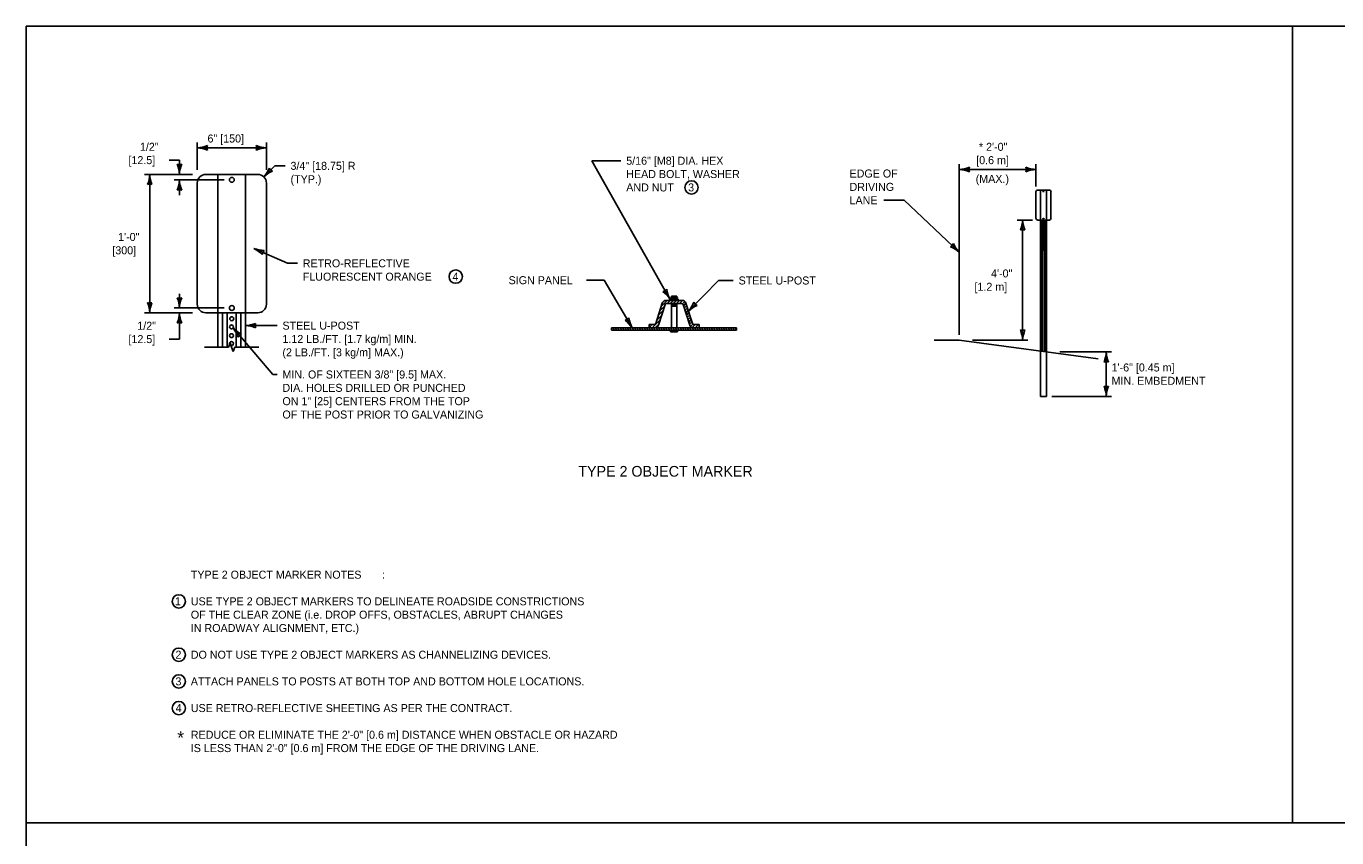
# Model space of a CAD drawing. Extents: x 49991.4 to 50024.6, y 49987.6 to 50011.4.
# Drawn here: x 49999.38 to 50009.21, y 49992.92 to 49999 of the extents above; entities that cross this region are included whole.
import ezdxf

# ---------------------------------------------------------------- set-up
doc = ezdxf.new("R2010")
doc.units = 0
for name, color, linetype in [('Level 1', 7, 'Continuous'), ('Level 2', 7, 'Continuous'), ('Level 3', 7, 'Continuous'), ('Level 4', 7, 'Continuous'), ('Level 6', 7, 'Continuous')]:
    doc.layers.add(name, color=color, linetype=linetype)

msp = doc.modelspace()

# ---------------------------------------------------------------- linework, layer by layer
at = {"layer": 'Level 1'}
for p, q in [((50006.9969, 49996.563), (50006.9969, 49997.5461)), ((50007.0044, 49996.562), (50007.0044, 49997.5461)), ((50007.0194, 49996.56), (50007.0194, 49997.5461)), ((50007.0269, 49996.5592), (50007.0269, 49997.5461)), ((50004.1345, 49996.8647), (50004.1709, 49996.9011)), ((50004.1455, 49996.8987), (50004.1904, 49996.9437)), ((50004.1899, 49996.9202), (50004.2134, 49996.9437)), ((50004.2107, 49996.9538), (50004.2733, 49996.9538)), ((50004.2107, 49996.9538), (50004.2107, 49996.9437)), ((50004.2131, 49996.9202), (50004.2366, 49996.9437)), ((50004.2166, 49996.9648), (50004.2674, 49996.9648)), ((50004.2166, 49996.9648), (50004.2166, 49996.9538)), ((50004.2224, 49996.975), (50004.2615, 49996.975)), ((50004.2224, 49996.975), (50004.2224, 49996.9648)), ((50004.2322, 49996.9699), (50004.2518, 49996.9699)), ((50004.2322, 49996.9151), (50004.2518, 49996.9151)), ((50004.2322, 49996.9048), (50004.2518, 49996.9048)), ((50004.2334, 49996.9648), (50004.2334, 49996.9538)), ((50004.2362, 49996.9202), (50004.2597, 49996.9437)), ((50004.2505, 49996.9648), (50004.2505, 49996.9538)), ((50004.2592, 49996.9202), (50004.2827, 49996.9437)), ((50004.2615, 49996.975), (50004.2615, 49996.9648)), ((50004.2674, 49996.9648), (50004.2674, 49996.9538)), ((50004.2733, 49996.9538), (50004.2733, 49996.9437)), ((50004.2822, 49996.9202), (50004.3056, 49996.9435)), ((50004.3039, 49996.9188), (50004.3217, 49996.9366)), ((50004.3121, 49996.9039), (50004.3308, 49996.9225)), ((50004.3178, 49996.8865), (50004.3364, 49996.9051)), ((50004.3234, 49996.8691), (50004.342, 49996.8878)), ((50000.8548, 49996.5938), (50000.8548, 49996.8508)), ((50000.8894, 49996.5938), (50000.8894, 49996.8508)), ((50000.9587, 49996.5938), (50000.9587, 49996.8508)), ((50000.9933, 49996.5938), (50000.9933, 49996.8508)), ((50004.0775, 49996.7385), (50004.138, 49996.7989)), ((50004.1124, 49996.7964), (50004.149, 49996.833)), ((50004.1234, 49996.8305), (50004.1599, 49996.8669)), ((50004.329, 49996.8517), (50004.3476, 49996.8704)), ((50004.3347, 49996.8342), (50004.3533, 49996.8528)), ((50004.3403, 49996.8168), (50004.3589, 49996.8355)), ((50004.3459, 49996.7994), (50004.3645, 49996.8181)), ((50004.3516, 49996.7819), (50004.3702, 49996.8005)), ((50004.3572, 49996.7645), (50004.3758, 49996.7831)), ((50003.7732, 49996.7272), (50003.7796, 49996.7209)), ((50003.7799, 49996.7385), (50003.7976, 49996.7209)), ((50003.7979, 49996.7385), (50003.8156, 49996.7209)), ((50003.8159, 49996.7385), (50003.8336, 49996.7209)), ((50003.8339, 49996.7385), (50003.8516, 49996.7209)), ((50003.8519, 49996.7385), (50003.8696, 49996.7209)), ((50003.8699, 49996.7385), (50003.8876, 49996.7209)), ((50003.8879, 49996.7385), (50003.9056, 49996.7209)), ((50003.9059, 49996.7385), (50003.9236, 49996.7209)), ((50003.9239, 49996.7385), (50003.9416, 49996.7209)), ((50003.9419, 49996.7385), (50003.9596, 49996.7209)), ((50003.9599, 49996.7385), (50003.9776, 49996.7209)), ((50003.9779, 49996.7385), (50003.9956, 49996.7209)), ((50003.9959, 49996.7385), (50004.0136, 49996.7209)), ((50004.0139, 49996.7385), (50004.0316, 49996.7209)), ((50004.0319, 49996.7385), (50004.0496, 49996.7209)), ((50004.0499, 49996.7385), (50004.0676, 49996.7209)), ((50004.0545, 49996.7385), (50004.078, 49996.762)), ((50004.0679, 49996.7385), (50004.0856, 49996.7209)), ((50004.0859, 49996.7385), (50004.1036, 49996.7209)), ((50004.1008, 49996.7387), (50004.127, 49996.765)), ((50004.1039, 49996.7385), (50004.1216, 49996.7209)), ((50004.1219, 49996.7385), (50004.1396, 49996.7209)), ((50004.1399, 49996.7385), (50004.1576, 49996.7209)), ((50004.1579, 49996.7385), (50004.1756, 49996.7209)), ((50004.1759, 49996.7385), (50004.1936, 49996.7209)), ((50004.1939, 49996.7385), (50004.2116, 49996.7209)), ((50004.2119, 49996.7385), (50004.2296, 49996.7209)), ((50004.2152, 49996.7209), (50004.2152, 49996.7091)), ((50004.2152, 49996.7091), (50004.2666, 49996.7091)), ((50004.2299, 49996.7385), (50004.2476, 49996.7209)), ((50004.2333, 49996.7209), (50004.2333, 49996.7091)), ((50004.2479, 49996.7385), (50004.2656, 49996.7209)), ((50004.251, 49996.7209), (50004.251, 49996.7091)), ((50004.2659, 49996.7385), (50004.2836, 49996.7209)), ((50004.2666, 49996.7209), (50004.2666, 49996.7091)), ((50004.2839, 49996.7385), (50004.3016, 49996.7209)), ((50004.3019, 49996.7385), (50004.3196, 49996.7209)), ((50004.3199, 49996.7385), (50004.3376, 49996.7209)), ((50004.3379, 49996.7385), (50004.3556, 49996.7209)), ((50004.3559, 49996.7385), (50004.3736, 49996.7209)), ((50004.3645, 49996.7489), (50004.382, 49996.7664)), ((50004.3739, 49996.7385), (50004.3916, 49996.7209)), ((50004.3784, 49996.7397), (50004.4006, 49996.762)), ((50004.3919, 49996.7385), (50004.4096, 49996.7209)), ((50004.4003, 49996.7385), (50004.4238, 49996.762)), ((50004.4099, 49996.7385), (50004.4276, 49996.7209)), ((50004.4233, 49996.7385), (50004.4295, 49996.7447)), ((50004.4279, 49996.7385), (50004.4456, 49996.7209)), ((50004.4459, 49996.7385), (50004.4636, 49996.7209)), ((50004.4639, 49996.7385), (50004.4816, 49996.7209)), ((50004.4819, 49996.7385), (50004.4996, 49996.7209)), ((50004.4999, 49996.7385), (50004.5176, 49996.7209)), ((50004.5179, 49996.7385), (50004.5356, 49996.7209)), ((50004.5359, 49996.7385), (50004.5536, 49996.7209)), ((50004.5539, 49996.7385), (50004.5716, 49996.7209)), ((50004.5719, 49996.7385), (50004.5896, 49996.7209)), ((50004.5899, 49996.7385), (50004.6076, 49996.7209)), ((50004.6079, 49996.7385), (50004.6256, 49996.7209)), ((50004.6259, 49996.7385), (50004.6436, 49996.7209)), ((50004.6439, 49996.7385), (50004.6616, 49996.7209)), ((50004.6619, 49996.7385), (50004.6796, 49996.7209)), ((50004.6799, 49996.7385), (50004.6976, 49996.7209)), ((50004.6979, 49996.7385), (50004.7106, 49996.7258))]:
    msp.add_line(p, q, dxfattribs=at)
msp.add_lwpolyline([(49999.3835, 49998.9992), (50016.7501, 49998.9992), (50016.7501, 49987.7988), (49999.3835, 49987.7988)], close=True, dxfattribs=at)
for centre, radius in [((50007.0116, 49997.5231), 0.00318), ((50007.0116, 49997.509), 0.00318), ((50007.0116, 49997.4956), 0.00318), ((50007.0116, 49997.4823), 0.00318), ((50007.0116, 49997.4689), 0.00318), ((50007.012, 49997.5365), 0.00318), ((50007.0116, 49997.4556), 0.00318), ((50007.0116, 49997.4422), 0.00318), ((50007.0116, 49997.4289), 0.00318), ((50007.0116, 49997.4155), 0.00318), ((50007.0116, 49997.4022), 0.00318), ((50007.0116, 49997.3888), 0.00318), ((50007.0116, 49997.3755), 0.00318), ((50007.0116, 49997.3621), 0.00318), ((50007.0116, 49997.3488), 0.00318), ((50007.0116, 49997.3354), 0.00318), ((50007.0116, 49997.3221), 0.00318), ((50000.9247, 49996.8065), 0.0146), ((50000.9229, 49996.745), 0.0146), ((50000.9229, 49996.6798), 0.0146)]:
    msp.add_circle(centre, radius, dxfattribs=at)
msp.add_arc((50000.9229, 49996.6201), 0.0146, 258.06006, 198.90955, dxfattribs=at)
at = {"layer": 'Level 2'}
for p, q in [((50008.8796, 49998.9992), (50008.8796, 49993.0275)), ((50000.7308, 49997.8885), (50001.1201, 49997.8885)), ((50000.666, 49996.9156), (50000.666, 49997.8237)), ((50001.185, 49997.8237), (50001.185, 49996.9156)), ((50006.97, 49997.7711), (50007.0544, 49997.7711)), ((50006.9559, 49997.5601), (50006.9559, 49997.757)), ((50007.0684, 49997.757), (50007.0684, 49997.5601)), ((50007.0544, 49997.5461), (50006.97, 49997.5461)), ((50006.9894, 49996.564), (50006.9894, 49997.5461)), ((50007.0344, 49996.558), (50007.0344, 49997.5461)), ((50004.1534, 49996.9234), (50004.1039, 49996.7701)), ((50004.1744, 49996.9121), (50004.125, 49996.7587)), ((50004.1812, 49996.9437), (50004.3027, 49996.9437)), ((50004.1856, 49996.9202), (50004.2984, 49996.9202)), ((50004.2224, 49996.9202), (50004.2224, 49996.7385)), ((50004.2224, 49996.9099), (50004.2615, 49996.9099)), ((50004.2224, 49996.8997), (50004.2615, 49996.8997)), ((50004.2615, 49996.9202), (50004.2615, 49996.7385)), ((50004.3095, 49996.9121), (50004.3591, 49996.7587)), ((50004.3305, 49996.9235), (50004.38, 49996.7701)), ((50001.1201, 49996.8508), (50000.7308, 49996.8508)), ((50000.8203, 49996.5938), (50000.8203, 49996.8508)), ((50001.0278, 49996.5938), (50001.0278, 49996.8508)), ((50003.7732, 49996.7385), (50003.7732, 49996.7209)), ((50003.7732, 49996.7385), (50004.7107, 49996.7385)), ((50003.7732, 49996.7209), (50004.7107, 49996.7209)), ((50004.0544, 49996.762), (50004.0544, 49996.7385)), ((50004.0544, 49996.762), (50004.0928, 49996.762)), ((50004.0971, 49996.7385), (50004.0544, 49996.7385)), ((50004.3868, 49996.7385), (50004.4295, 49996.7385)), ((50004.3912, 49996.762), (50004.4295, 49996.762)), ((50004.4295, 49996.762), (50004.4295, 49996.7385)), ((50004.7107, 49996.7385), (50004.7107, 49996.7209)), ((50006.3806, 49996.6461), (50006.1934, 49996.6461)), ((50006.3806, 49996.6461), (50007.4228, 49996.5056)), ((49999.3835, 49993.0275), (50016.7501, 49993.0275))]:
    msp.add_line(p, q, dxfattribs=at)
for centre, radius in [((50000.9255, 49997.8474), 0.0183), ((50004.3724, 49997.7909), 0.05), ((50007.0122, 49997.7621), 0.00397), ((50007.0121, 49997.554), 0.00397), ((50002.6043, 49997.1218), 0.05), ((50000.9251, 49996.8873), 0.0183), ((50000.5279, 49994.6878), 0.05), ((50000.5279, 49994.2878), 0.05), ((50000.5279, 49994.0878), 0.05), ((50000.5279, 49993.8878), 0.05)]:
    msp.add_circle(centre, radius, dxfattribs=at)
for centre, radius, start, end in [((50000.7308, 49997.8237), 0.0648, 90, 180), ((50001.1201, 49997.8237), 0.0648, 0, 90), ((50006.97, 49997.757), 0.0141, 90, 180), ((50007.0544, 49997.757), 0.0141, 0, 90), ((50006.97, 49997.5601), 0.0141, 180, 270), ((50007.0544, 49997.5601), 0.0141, 270, 0), ((50000.7308, 49996.9156), 0.0648, 180, 270), ((50001.1201, 49996.9156), 0.0648, 270, 0), ((50004.1813, 49996.9144), 0.0293, 90, 162.11094), ((50004.1856, 49996.9084), 0.0117, 90, 162.11105), ((50004.2983, 49996.9084), 0.0117, 17.88895, 90), ((50004.3027, 49996.9144), 0.0293, 17.88906, 90), ((50004.0928, 49996.7737), 0.0117, 270, 342.11094), ((50004.0972, 49996.7677), 0.0293, 270, 342.11105), ((50004.3869, 49996.7677), 0.0293, 197.88804, 270), ((50004.3912, 49996.7737), 0.0117, 197.88906, 270.15232)]:
    msp.add_arc(centre, radius, start, end, dxfattribs=at)
at = {"layer": 'Level 3'}
for p, q in [((50000.666, 49997.9237), (50000.666, 49998.1275)), ((50001.185, 49998.0875), (50000.666, 49998.0875)), ((50001.185, 49997.9237), (50001.185, 49998.1275)), ((50000.4544, 49997.9954), (50000.5325, 49997.9954)), ((50000.5325, 49997.8885), (50000.5325, 49997.9954)), ((50004.2107, 49996.9538), (50003.6257, 49997.9909)), ((50003.6257, 49997.9909), (50003.8432, 49997.9909)), ((50006.3806, 49997.9651), (50006.3806, 49996.6861)), ((50006.9559, 49997.797), (50006.9559, 49997.9651)), ((50000.6308, 49997.8885), (50000.2698, 49997.8885)), ((50000.3098, 49996.8508), (50000.3098, 49997.8885)), ((50001.1652, 49997.8703), (50001.2474, 49997.9525)), ((50001.2474, 49997.9525), (50001.3255, 49997.9525)), ((50006.9559, 49997.9251), (50006.3806, 49997.9251)), ((50000.8672, 49997.8474), (50000.4925, 49997.8474)), ((50000.5325, 49997.7837), (50000.5325, 49997.8474)), ((50000.5325, 49997.8474), (50000.5325, 49997.7329)), ((50005.9678, 49997.695), (50005.8146, 49997.695)), ((50005.9678, 49997.695), (50006.3806, 49997.3054)), ((50006.93, 49997.5461), (50006.8159, 49997.5461)), ((50006.8559, 49997.5461), (50006.8559, 49996.6461)), ((50001.3427, 49997.2218), (50001.0908, 49997.3336)), ((50001.4174, 49997.2218), (50001.3427, 49997.2218)), ((50003.7178, 49997.0952), (50003.5849, 49997.0952)), ((50003.7178, 49997.0952), (50003.9273, 49996.7385)), ((50004.5741, 49997.0931), (50004.3497, 49996.8639)), ((50004.5741, 49997.0931), (50004.6858, 49997.0931)), ((50000.5325, 49996.8873), (50000.5325, 49996.9943)), ((50000.8668, 49996.8873), (50000.4925, 49996.8873)), ((50000.5325, 49996.9555), (50000.5325, 49996.8918)), ((50000.6308, 49996.8508), (50000.2698, 49996.8508)), ((50000.5325, 49996.8508), (50000.5325, 49996.6538)), ((50001.2336, 49996.3884), (50000.9353, 49996.7373)), ((50001.2649, 49996.7547), (50001.0278, 49996.7547)), ((50000.4544, 49996.6538), (50000.5325, 49996.6538)), ((50006.4806, 49996.6461), (50006.8959, 49996.6461)), ((50007.1344, 49996.558), (50007.5229, 49996.558)), ((50007.4829, 49996.2242), (50007.4829, 49996.558)), ((50001.2649, 49996.3884), (50001.2336, 49996.3884)), ((50007.0744, 49996.2242), (50007.5229, 49996.2242))]:
    msp.add_line(p, q, dxfattribs=at)
for centre, radius, start, end in [((50000.6545, 49998.3203), 0.233, 272.82731, 292.07716), ((50000.6568, 49997.8654), 0.2223, 67.45601, 87.63952), ((50000.7942, 49998.0875), 0.0548, 162.13882, 197.86118), ((50001.1941, 49998.3097), 0.2223, 247.45601, 267.63952), ((50001.0568, 49998.0875), 0.0548, 342.13882, 17.86118), ((50001.1965, 49997.8548), 0.233, 92.82731, 112.07716), ((50000.5325, 49998.0168), 0.0548, 252.13882, 287.86118), ((50000.2998, 49997.877), 0.233, 2.82731, 22.07716), ((50000.7547, 49997.8794), 0.2223, 157.45601, 177.63952), ((50000.0876, 49997.8977), 0.2223, 337.45601, 357.63952), ((50000.5425, 49997.9), 0.233, 182.82731, 202.07716), ((50000.9925, 49998.0267), 0.233, 317.82731, 337.07716), ((50001.3158, 49997.7068), 0.2223, 112.45601, 132.63952), ((50001.2559, 49997.961), 0.0548, 207.13882, 242.86118), ((50006.3691, 49998.1578), 0.233, 272.82731, 292.07716), ((50006.3714, 49997.703), 0.2223, 67.45601, 87.63952), ((50006.5088, 49997.9251), 0.0548, 162.13882, 197.86118), ((50006.9651, 49998.1473), 0.2223, 247.45601, 267.63952), ((50006.8277, 49997.9251), 0.0548, 342.13882, 17.86118), ((50006.9674, 49997.6924), 0.233, 92.82731, 112.07716), ((50000.3098, 49997.7603), 0.0548, 72.13882, 107.86118), ((50000.3104, 49997.8565), 0.2223, 337.45601, 357.63952), ((50000.5325, 49997.7192), 0.0548, 72.13882, 107.86118), ((50000.7652, 49997.8589), 0.233, 182.82731, 202.07716), ((50006.6338, 49997.5552), 0.2223, 337.45601, 357.63952), ((50006.8559, 49997.4179), 0.0548, 72.13882, 107.86118), ((50007.0886, 49997.5576), 0.233, 182.82731, 202.07716), ((50000.9923, 49997.1343), 0.2223, 43.52413, 63.70764), ((50001.1747, 49997.551), 0.233, 248.89543, 268.14528), ((50001.2079, 49997.2816), 0.0548, 138.20694, 173.9293), ((50006.2873, 49997.3934), 0.0548, 298.79497, 334.51733), ((50006.2292, 49997.1283), 0.233, 49.48346, 68.73331), ((50006.5397, 49997.4607), 0.2223, 204.11216, 224.29567), ((50004.1477, 49997.0654), 0.0548, 281.56499, 317.28735), ((50004.0137, 49996.8294), 0.233, 32.25348, 51.50333), ((50004.4087, 49997.0549), 0.2223, 186.88218, 207.06569), ((50000.3098, 49996.979), 0.0548, 252.13882, 287.86118), ((50000.0771, 49996.8393), 0.233, 2.82731, 22.07716), ((50000.5319, 49996.8416), 0.2223, 157.45601, 177.63952), ((50000.3104, 49996.8781), 0.2223, 2.36048, 22.54399), ((50000.5325, 49997.0155), 0.0548, 252.13882, 287.86118), ((50000.7652, 49996.8758), 0.233, 157.92284, 177.17269), ((50004.1754, 49997.0185), 0.233, 318.43466, 337.68451), ((50004.5021, 49996.7019), 0.2223, 113.06336, 133.24687), ((50004.4394, 49996.9555), 0.0548, 207.74617, 243.46853), ((50000.2998, 49996.8623), 0.233, 337.92284, 357.17269), ((50000.7547, 49996.8599), 0.2223, 182.36048, 202.54399), ((50003.8624, 49996.849), 0.0548, 282.56173, 318.28409), ((50003.7325, 49996.6107), 0.233, 33.25022, 52.50007), ((50004.1235, 49996.8431), 0.2223, 187.87892, 208.06243), ((50000.5325, 49996.7226), 0.0548, 72.13882, 107.86118), ((50000.7605, 49996.5999), 0.2223, 17.98835, 38.17186), ((50001.1047, 49996.8972), 0.233, 223.35965, 242.6095), ((50001.0186, 49996.6398), 0.0548, 112.67116, 148.39352), ((50001.0163, 49996.9874), 0.233, 272.82731, 292.07716), ((50001.0187, 49996.5326), 0.2223, 67.45601, 87.63952), ((50001.156, 49996.7547), 0.0548, 162.13882, 197.86118), ((50006.8559, 49996.7743), 0.0548, 252.13882, 287.86118), ((50006.6232, 49996.6346), 0.233, 2.82731, 22.07716), ((50007.0781, 49996.6369), 0.2223, 157.45601, 177.63952), ((50007.2608, 49996.5671), 0.2223, 337.45601, 357.63952), ((50007.7156, 49996.5695), 0.233, 182.82731, 202.07716), ((50007.4829, 49996.4297), 0.0548, 72.13882, 107.86118), ((50007.4829, 49996.3524), 0.0548, 252.13882, 287.86118), ((50007.2502, 49996.2127), 0.233, 2.82731, 22.07716), ((50007.7051, 49996.2151), 0.2223, 157.45601, 177.63952)]:
    msp.add_arc(centre, radius, start, end, dxfattribs=at)
at = {"layer": 'Level 4'}
for p, q in [((50000.8203, 49996.8508), (50000.8203, 49997.8885)), ((50001.0278, 49996.8508), (50001.0278, 49997.8885)), ((50006.9894, 49997.5461), (50006.9894, 49997.7711)), ((50007.0344, 49997.5461), (50007.0344, 49997.7711)), ((50006.9894, 49996.564), (50006.9894, 49996.2242)), ((50007.0344, 49996.558), (50007.0344, 49996.2242)), ((50006.9894, 49996.2242), (50007.0344, 49996.2242))]:
    msp.add_line(p, q, dxfattribs=at)
at = {"layer": 'Level 6'}
for p, q in [((50000.7203, 49996.5938), (50000.9014, 49996.5938)), ((50000.9127, 49996.6258), (50000.9014, 49996.5938)), ((50000.9127, 49996.6258), (50000.9241, 49996.5938)), ((50000.9241, 49996.5938), (50000.9354, 49996.5618)), ((50000.9468, 49996.5938), (50000.9354, 49996.5618)), ((50000.9468, 49996.5938), (50001.1278, 49996.5938))]:
    msp.add_line(p, q, dxfattribs=at)

# ---------------------------------------------------------------- texts
at = {"layer": 'Level 2'}
for s, height, p in [('6" [150]', 0.06, (50000.743, 49998.1275)), ('* 2\'-0"', 0.06, (50006.528, 49998.0651)), ('5/16" [M8] DIA. HEX', 0.06, (50003.8832, 49997.9609)), ('[0.6 m]', 0.06, (50006.5076, 49997.9651)), ('HEAD BOLT, WASHER', 0.06, (50003.8832, 49997.8609)), ('EDGE OF', 0.06, (50005.5577, 49997.865)), ('(MAX.)', 0.06, (50006.5038, 49997.8251)), ('AND NUT', 0.06, (50003.8832, 49997.7609)), ('3', 0.06, (50004.3472, 49997.7609)), ('DRIVING', 0.06, (50005.5577, 49997.765)), ('LANE', 0.06, (50005.5577, 49997.665)), ('RETRO-REFLECTIVE', 0.06, (50001.4574, 49997.1918)), ('4\'-0"', 0.06, (50006.619, 49997.1161)), ('FLUORESCENT ORANGE', 0.06, (50001.4574, 49997.0918)), ('4', 0.06, (50002.5803, 49997.0918)), ('SIGN PANEL', 0.06, (50003.0009, 49997.0652)), ('STEEL U-POST', 0.06, (50004.7258, 49997.0631)), ('[1.2 m]', 0.06, (50006.4946, 49997.0161)), ('STEEL U-POST', 0.06, (50001.3049, 49996.7247)), ('1.12 LB./FT. [1.7 kg/m] MIN.', 0.06, (50001.3049, 49996.6247)), ('(2 LB./FT. [3 kg/m] MAX.)', 0.06, (50001.3049, 49996.5247)), ('MIN. OF SIXTEEN 3/8" [9.5] MAX. ', 0.06, (50001.3049, 49996.3584)), ('1\'-6" [0.45 m]', 0.06, (50007.5229, 49996.4111)), ('DIA. HOLES DRILLED OR PUNCHED', 0.06, (50001.3049, 49996.2584)), ('MIN. EMBEDMENT', 0.06, (50007.5229, 49996.3111)), ('ON 1" [25] CENTERS FROM THE TOP', 0.06, (50001.3049, 49996.1584)), ('OF THE POST PRIOR TO GALVANIZING', 0.06, (50001.3049, 49996.0584)), ('TYPE 2 OBJECT MARKER', 0.08, (50003.5238, 49995.6227)), ('TYPE 2 OBJECT MARKER NOTES', 0.06, (50000.6179, 49994.8578)), (':', 0.06, (50002.0509, 49994.8578)), ('1', 0.06, (50000.4986, 49994.6578)), ('USE TYPE 2 OBJECT MARKERS TO DELINEATE ROADSIDE CONSTRICTIONS', 0.06, (50000.6179, 49994.6578)), ('OF THE CLEAR ZONE (i.e. DROP OFFS, OBSTACLES, ABRUPT CHANGES', 0.06, (50000.6179, 49994.5578)), ('IN ROADWAY ALIGNMENT, ETC.)  ', 0.06, (50000.6179, 49994.4578)), ('2', 0.06, (50000.5028, 49994.2578)), ('DO NOT USE TYPE 2 OBJECT MARKERS AS CHANNELIZING DEVICES.', 0.06, (50000.6179, 49994.2578)), ('3', 0.06, (50000.5027, 49994.0578)), ('ATTACH PANELS TO POSTS AT BOTH TOP AND BOTTOM HOLE LOCATIONS.', 0.06, (50000.6179, 49994.0578)), ('4', 0.06, (50000.504, 49993.8578)), ('USE RETRO-REFLECTIVE SHEETING AS PER THE CONTRACT. ', 0.06, (50000.6179, 49993.8578)), ('*', 0.0963, (50000.5167, 49993.6177)), ('REDUCE OR ELIMINATE THE 2\'-0" [0.6 m] DISTANCE WHEN OBSTACLE OR HAZARD', 0.06, (50000.6179, 49993.6578)), ('IS LESS THAN 2\'-0" [0.6 m] FROM THE EDGE OF THE DRIVING LANE.', 0.06, (50000.6179, 49993.5578))]:
    msp.add_text(s, height=height, dxfattribs=at).set_placement(p)
for s, rotation, p in [('1/2"', 0.03312, (50000.2362, 49998.0653)), ('[12.5]', 0.03312, (50000.1504, 49997.9652)), ('3/4" [18.75] R', 0.02011, (50001.3655, 49997.9225)), ('(TYP.)', 0.02011, (50001.3656, 49997.8225)), ('1\'-0"', 0.08467, (50000.0727, 49997.3894)), ('[300]', 0.08467, (50000.0294, 49997.2893)), (' 1/2"', 359.96688, (50000.1942, 49996.7239)), ('[12.5]', 359.96688, (50000.1504, 49996.6239))]:
    msp.add_text(s, height=0.06, rotation=rotation, dxfattribs=at).set_placement(p)

doc.saveas('drawing.dxf')
